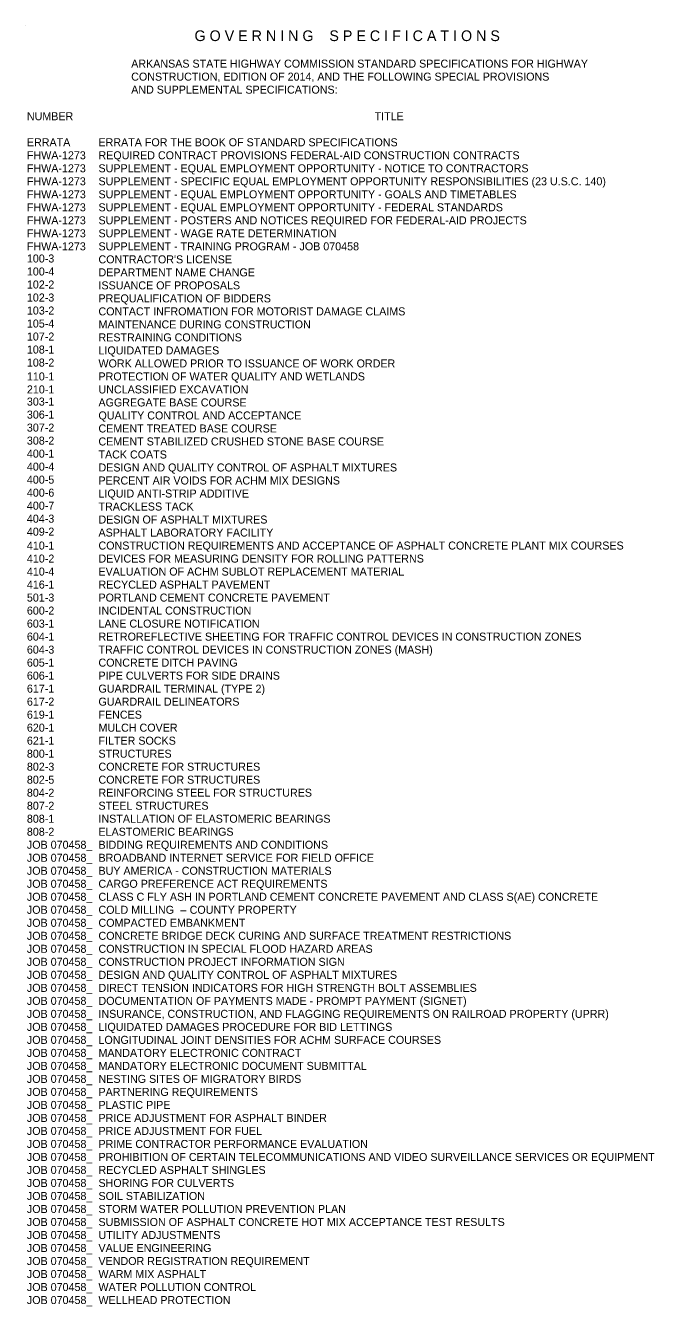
# Model space of a CAD drawing. Extents: x -2857 to 1648, y -1031 to 968.
# Drawn here: x -2857 to -1915, y -952 to 968 of the extents above; entities that cross this region are included whole.
import ezdxf

# ---------------------------------------------------------------- set-up
doc = ezdxf.new("R2010")
doc.units = 0
doc.layers.add('Default', color=7, linetype='Continuous')

msp = doc.modelspace()

# ---------------------------------------------------------------- linework, layer by layer
at = {"layer": 'Default'}
msp.add_line((-2857.1, 967.9), (-2857.1, 967.9), dxfattribs=at)

# ---------------------------------------------------------------- texts
for s, height, p in [('G O V E R N I N G    S P E C I F I C A T I O N S', 16, (-2603.9, 944.7)), ('           ARKANSAS STATE HIGHWAY COMMISSION STANDARD SPECIFICATIONS FOR HIGHWAY', 12, (-2747.9, 904.9)), ('           CONSTRUCTION, EDITION OF 2014, AND THE FOLLOWING SPECIAL PROVISIONS', 12, (-2747.9, 885.4)), ('           AND SUPPLEMENTAL SPECIFICATIONS:', 12, (-2747.9, 865.9)), ('NUMBER', 12, (-2855.2, 826)), ('TITLE', 12, (-2334, 826)), ('ERRATA', 12, (-2855.2, 787)), ('ERRATA FOR THE BOOK OF STANDARD SPECIFICATIONS', 12, (-2747.9, 787)), ('FHWA-1273', 12, (-2855.2, 767.5)), ('REQUIRED CONTRACT PROVISIONS FEDERAL-AID CONSTRUCTION CONTRACTS', 12, (-2747.9, 767.5)), ('FHWA-1273', 12, (-2855.2, 748)), ('SUPPLEMENT - EQUAL EMPLOYMENT OPPORTUNITY - NOTICE TO CONTRACTORS', 12, (-2747.9, 748)), ('FHWA-1273', 12, (-2855.2, 728.5)), ('SUPPLEMENT - SPECIFIC EQUAL EMPLOYMENT OPPORTUNITY RESPONSIBILITIES (23 U.S.C. 140)', 12, (-2747.9, 728.5)), ('FHWA-1273', 12, (-2855.2, 709)), ('SUPPLEMENT - EQUAL EMPLOYMENT OPPORTUNITY - GOALS AND TIMETABLES ', 12, (-2747.9, 709)), ('FHWA-1273', 12, (-2855.2, 689.5)), ('SUPPLEMENT - EQUAL EMPLOYMENT OPPORTUNITY - FEDERAL STANDARDS', 12, (-2747.9, 689.5)), ('FHWA-1273', 12, (-2855.2, 670)), ('SUPPLEMENT - POSTERS AND NOTICES REQUIRED FOR FEDERAL-AID PROJECTS', 12, (-2747.9, 670)), ('FHWA-1273', 12, (-2855.2, 650.5)), ('SUPPLEMENT - WAGE RATE DETERMINATION', 12, (-2747.9, 650.5)), ('FHWA-1273', 12, (-2855.2, 631)), ('SUPPLEMENT - TRAINING PROGRAM - JOB 070458', 12, (-2747.9, 631)), ('100-3', 12, (-2855.2, 612.8)), ("CONTRACTOR'S LICENSE", 12, (-2747.9, 611.5)), ('100-4', 12, (-2855.2, 593.3)), ('DEPARTMENT NAME CHANGE', 12, (-2747.9, 592)), ('102-2', 12, (-2855.2, 573.8)), ('ISSUANCE OF PROPOSALS', 12, (-2747.9, 572.5)), ('102-3', 12, (-2855.2, 554.3)), ('PREQUALIFICATION OF BIDDERS', 12, (-2747.9, 553)), ('103-2', 12, (-2855.2, 534.8)), ('CONTACT INFROMATION FOR MOTORIST DAMAGE CLAIMS', 12, (-2747.9, 533.5)), ('105-4', 12, (-2855.2, 515.3)), ('MAINTENANCE DURING CONSTRUCTION', 12, (-2747.9, 514)), ('107-2', 12, (-2855.2, 495.8)), ('RESTRAINING CONDITIONS', 12, (-2747.9, 494.5)), ('108-1', 12, (-2855.2, 476.3)), ('LIQUIDATED DAMAGES', 12, (-2747.9, 475)), ('108-2', 12, (-2855.2, 456.8)), ('WORK ALLOWED PRIOR TO ISSUANCE OF WORK ORDER', 12, (-2747.9, 455.5)), ('110-1', 12, (-2855.2, 436)), ('PROTECTION OF WATER QUALITY AND WETLANDS', 12, (-2747.9, 436)), ('210-1', 12, (-2855.2, 416.5)), ('UNCLASSIFIED EXCAVATION', 12, (-2747.9, 416.5)), ('303-1', 12, (-2855.2, 398.3)), ('AGGREGATE BASE COURSE', 12, (-2747.9, 397)), ('306-1', 12, (-2855.2, 378.8)), ('QUALITY CONTROL AND ACCEPTANCE', 12, (-2747.9, 377.5)), ('307-2', 12, (-2855.2, 359.3)), ('CEMENT TREATED BASE COURSE', 12, (-2747.9, 358)), ('308-2', 12, (-2855.2, 339.8)), ('CEMENT STABILIZED CRUSHED STONE BASE COURSE', 12, (-2747.9, 338.5)), ('400-1', 12, (-2855.2, 320.3)), ('TACK COATS', 12, (-2747.9, 319)), ('400-4', 12, (-2855.2, 300.8)), ('DESIGN AND QUALITY CONTROL OF ASPHALT MIXTURES', 12, (-2747.9, 299.5)), ('400-5', 12, (-2855.2, 281.3)), ('PERCENT AIR VOIDS FOR ACHM MIX DESIGNS', 12, (-2747.9, 280)), ('400-6', 12, (-2855.2, 261.8)), ('LIQUID ANTI-STRIP ADDITIVE', 12, (-2747.9, 260.5)), ('400-7', 12, (-2855.2, 242.3)), ('TRACKLESS TACK', 12, (-2747.9, 241)), ('404-3', 12, (-2855.2, 222.8)), ('DESIGN OF ASPHALT MIXTURES', 12, (-2747.9, 221.5)), ('409-2', 12, (-2855.2, 203.3)), ('ASPHALT LABORATORY FACILITY', 12, (-2747.9, 202)), ('410-1', 12, (-2855.2, 182.5)), ('CONSTRUCTION REQUIREMENTS AND ACCEPTANCE OF ASPHALT CONCRETE PLANT MIX COURSES', 12, (-2747.9, 182.5)), ('410-2', 12, (-2855.2, 163)), ('DEVICES FOR MEASURING DENSITY FOR ROLLING PATTERNS', 12, (-2747.9, 163)), ('410-4', 12, (-2855.2, 143.5)), ('EVALUATION OF ACHM SUBLOT REPLACEMENT MATERIAL', 12, (-2747.9, 143.5)), ('416-1', 12, (-2855.2, 124)), ('RECYCLED ASPHALT PAVEMENT', 12, (-2747.9, 124)), ('501-3', 12, (-2855.2, 104.5)), ('PORTLAND CEMENT CONCRETE PAVEMENT', 12, (-2747.9, 104.5)), ('600-2', 12, (-2855.2, 85)), ('INCIDENTAL CONSTRUCTION', 12, (-2747.9, 85)), ('603-1', 12, (-2855.2, 65.5)), ('LANE CLOSURE NOTIFICATION', 12, (-2747.9, 65.5)), ('604-1', 12, (-2855.2, 46)), ('RETROREFLECTIVE SHEETING FOR TRAFFIC CONTROL DEVICES IN CONSTRUCTION ZONES', 12, (-2747.9, 46)), ('604-3', 12, (-2855.2, 26.5)), ('TRAFFIC CONTROL DEVICES IN CONSTRUCTION ZONES (MASH)', 12, (-2747.9, 26.5)), ('605-1', 12, (-2855.2, 7)), ('CONCRETE DITCH PAVING', 12, (-2747.9, 7)), ('606-1', 12, (-2855.2, -12.5)), ('PIPE CULVERTS FOR SIDE DRAINS', 12, (-2747.9, -12.5)), ('617-1', 12, (-2855.2, -32)), ('GUARDRAIL TERMINAL (TYPE 2)', 12, (-2747.9, -32)), ('617-2', 12, (-2855.2, -51.5)), ('GUARDRAIL DELINEATORS', 12, (-2747.9, -51.5)), ('619-1', 12, (-2855.2, -71)), ('FENCES', 12, (-2747.9, -71)), ('620-1', 12, (-2855.2, -90.5)), ('MULCH COVER', 12, (-2747.9, -90.5)), ('621-1', 12, (-2855.2, -110)), ('FILTER SOCKS', 12, (-2747.9, -110)), ('800-1', 12, (-2855.2, -129.5)), ('STRUCTURES', 12, (-2747.9, -129.5)), ('802-3', 12, (-2855.2, -149)), ('CONCRETE FOR STRUCTURES', 12, (-2747.9, -149)), ('802-5', 12, (-2855.2, -168.5)), ('CONCRETE FOR STRUCTURES', 12, (-2747.9, -168.5)), ('804-2', 12, (-2855.2, -188)), ('REINFORCING STEEL FOR STRUCTURES', 12, (-2747.9, -188)), ('807-2', 12, (-2855.2, -207.5)), ('STEEL STRUCTURES', 12, (-2747.9, -207.5)), ('808-1', 12, (-2855.2, -227)), ('INSTALLATION OF ELASTOMERIC BEARINGS', 12, (-2747.9, -227)), ('808-2', 12, (-2855.2, -246.5)), ('ELASTOMERIC BEARINGS', 12, (-2747.9, -246.5)), ('JOB 070458_', 12, (-2855.2, -266)), ('BIDDING REQUIREMENTS AND CONDITIONS', 12, (-2747.9, -266)), ('JOB 070458_', 12, (-2855.2, -285.5)), ('BROADBAND INTERNET SERVICE FOR FIELD OFFICE', 12, (-2747.9, -285.5)), ('JOB 070458_', 12, (-2855.2, -305)), ('BUY AMERICA - CONSTRUCTION MATERIALS', 12, (-2747.9, -305)), ('JOB 070458_', 12, (-2855.2, -324.5)), ('CARGO PREFERENCE ACT REQUIREMENTS', 12, (-2747.9, -324.5)), ('JOB 070458_', 12, (-2855.2, -344)), ('CLASS C FLY ASH IN PORTLAND CEMENT CONCRETE PAVEMENT AND CLASS S(AE) CONCRETE', 12, (-2747.9, -344)), ('JOB 070458_', 12, (-2855.2, -363.5)), ('COLD MILLING ', 12, (-2747.9, -363.5)), ('–', 12, (-2625, -363.5)), (' COUNTY PROPERTY', 12, (-2615.7, -363.5)), ('JOB 070458_', 12, (-2855.2, -383)), ('COMPACTED EMBANKMENT', 12, (-2747.9, -383)), ('JOB 070458_', 12, (-2855.2, -402.5)), ('CONCRETE BRIDGE DECK CURING AND SURFACE TREATMENT RESTRICTIONS', 12, (-2747.9, -402.5)), ('JOB 070458_', 12, (-2855.2, -422)), ('CONSTRUCTION IN SPECIAL FLOOD HAZARD AREAS', 12, (-2747.9, -422)), ('JOB 070458_', 12, (-2855.2, -441.5)), ('CONSTRUCTION PROJECT INFORMATION SIGN', 12, (-2747.9, -441.5)), ('JOB 070458_', 12, (-2855.2, -461)), ('DESIGN AND QUALITY CONTROL OF ASPHALT MIXTURES', 12, (-2747.9, -461)), ('JOB 070458_', 12, (-2855.2, -480.5)), ('DIRECT TENSION INDICATORS FOR HIGH STRENGTH BOLT ASSEMBLIES', 12, (-2747.9, -480.5)), ('JOB 070458_', 12, (-2855.2, -500)), ('DOCUMENTATION OF PAYMENTS MADE - PROMPT PAYMENT (SIGNET)', 12, (-2747.9, -500)), ('JOB 070458_', 12, (-2855.2, -519.5)), ('INSURANCE, CONSTRUCTION, AND FLAGGING REQUIREMENTS ON RAILROAD PROPERTY (UPRR)', 12, (-2747.9, -519.5)), ('JOB 070458_', 12, (-2855.2, -539)), ('LIQUIDATED DAMAGES PROCEDURE FOR BID LETTINGS', 12, (-2747.9, -539)), ('JOB 070458_', 12, (-2855.2, -558.5)), ('LONGITUDINAL JOINT DENSITIES FOR ACHM SURFACE COURSES', 12, (-2747.9, -558.5)), ('JOB 070458_', 12, (-2855.2, -578)), ('MANDATORY ELECTRONIC CONTRACT', 12, (-2747.9, -578)), ('JOB 070458_', 12, (-2855.2, -597.5)), ('MANDATORY ELECTRONIC DOCUMENT SUBMITTAL', 12, (-2747.9, -597.5)), ('JOB 070458_', 12, (-2855.2, -617)), ('NESTING SITES OF MIGRATORY BIRDS', 12, (-2747.9, -617)), ('JOB 070458_', 12, (-2855.2, -636.5)), ('PARTNERING REQUIREMENTS ', 12, (-2747.9, -636.5)), ('JOB 070458_', 12, (-2855.2, -656)), ('PLASTIC PIPE', 12, (-2747.9, -656)), ('JOB 070458_', 12, (-2855.2, -675.5)), ('PRICE ADJUSTMENT FOR ASPHALT BINDER', 12, (-2747.9, -675.5)), ('JOB 070458_', 12, (-2855.2, -695)), ('PRICE ADJUSTMENT FOR FUEL', 12, (-2747.9, -695)), ('JOB 070458_', 12, (-2855.2, -714.5)), ('PRIME CONTRACTOR PERFORMANCE EVALUATION', 12, (-2747.9, -714.5)), ('JOB 070458_', 12, (-2855.2, -734)), ('PROHIBITION OF CERTAIN TELECOMMUNICATIONS AND VIDEO SURVEILLANCE SERVICES OR EQUIPMENT', 12, (-2747.9, -734)), ('JOB 070458_', 12, (-2855.2, -753.5)), ('RECYCLED ASPHALT SHINGLES', 12, (-2747.9, -753.5)), ('JOB 070458_', 12, (-2855.2, -773)), ('SHORING FOR CULVERTS', 12, (-2747.9, -773)), ('JOB 070458_', 12, (-2855.2, -792.5)), ('SOIL STABILIZATION', 12, (-2747.9, -792.5)), ('JOB 070458_', 12, (-2855.2, -812)), ('STORM WATER POLLUTION PREVENTION PLAN', 12, (-2747.9, -812)), ('JOB 070458_', 12, (-2855.2, -831.5)), ('SUBMISSION OF ASPHALT CONCRETE HOT MIX ACCEPTANCE TEST RESULTS', 12, (-2747.9, -831.5)), ('JOB 070458_', 12, (-2855.2, -851)), ('UTILITY ADJUSTMENTS', 12, (-2747.9, -851)), ('JOB 070458_', 12, (-2855.2, -870.5)), ('VALUE ENGINEERING', 12, (-2747.9, -870.5)), ('JOB 070458_', 12, (-2855.2, -890)), ('VENDOR REGISTRATION REQUIREMENT', 12, (-2747.9, -890)), ('JOB 070458_', 12, (-2855.2, -909.5)), ('WARM MIX ASPHALT', 12, (-2747.9, -909.5)), ('JOB 070458_', 12, (-2855.2, -929)), ('WATER POLLUTION CONTROL', 12, (-2747.9, -929)), ('JOB 070458_', 12, (-2855.2, -948.5)), ('WELLHEAD PROTECTION', 12, (-2747.9, -948.5))]:
    msp.add_text(s, height=height, dxfattribs=at).set_placement(p)

doc.saveas('drawing.dxf')
